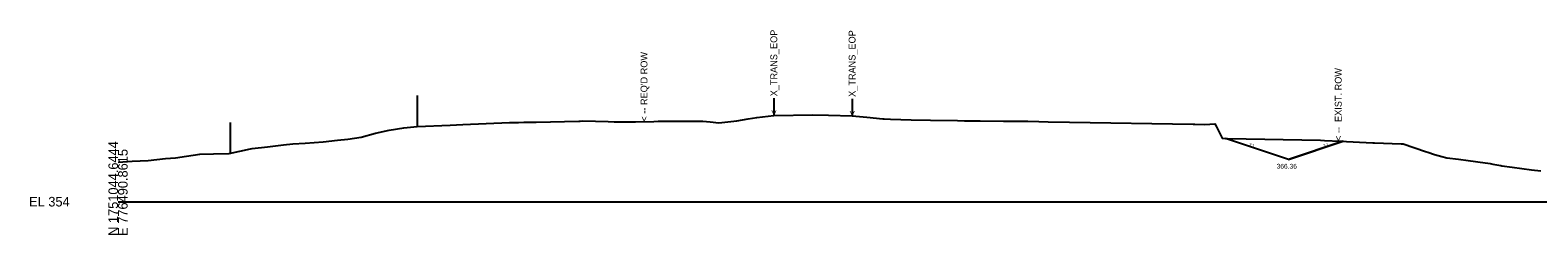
# Model space of a CAD drawing. Extents: x 776426 to 854588, y 1736205 to 1756790.
# Drawn here: x 805845.1 to 806285.9, y 1736205.1 to 1736264.9 of the extents above; entities that cross this region are included whole.
import ezdxf

# ---------------------------------------------------------------- set-up
doc = ezdxf.new("R2010")
doc.units = 0
for name, color, linetype in [('DTM CONTOURS_MAJOR_TX', 7, 'Continuous'), ('DTM_X_FLOW_ARROWS', 7, 'Continuous'), ('TRANS_UNPAVED_SHOULDERS', 7, 'Continuous'), ('X_TRANS_EOP', 7, 'Continuous'), ('XS_M_SHAPES_EARTHWORK', 7, 'Continuous'), ('XS_P_FINISHED_GRADE', 7, 'Continuous'), ('XS_P_ROW', 7, 'Continuous'), ('XS_P_TX_DCH', 7, 'Continuous'), ('XS_P_TX_FS_BS', 7, 'Continuous'), ('XS_X_PAVEMENT', 7, 'Continuous'), ('XS_X_ROW', 7, 'Continuous')]:
    doc.layers.add(name, color=color, linetype=linetype)

msp = doc.modelspace()

# ---------------------------------------------------------------- linework, layer by layer
at = {"layer": 'DTM CONTOURS_MAJOR_TX'}
msp.add_line((805870.79, 1736214.76), (806370.79, 1736214.76), dxfattribs=at)
at = {"layer": 'DTM_X_FLOW_ARROWS'}
msp.add_lwpolyline([(805870.79, 1736226.27), (805874.9, 1736226.59), (805879.55, 1736226.84), (805884.69, 1736227.34), (805887.54, 1736227.57), (805890.82, 1736228.02), (805892.77, 1736228.32), (805894.7, 1736228.63), (805898.66, 1736228.72), (805903.31, 1736228.83), (805909.55, 1736230.22), (805910.04, 1736230.33), (805914.5, 1736230.82), (805919.12, 1736231.33), (805921.85, 1736231.63), (805925.46, 1736231.88), (805930.79, 1736232.26), (805934.92, 1736232.77), (805937.97, 1736233.08), (805941.82, 1736233.66), (805946.1, 1736234.8), (805950.06, 1736235.63), (805954.35, 1736236.34), (805958.21, 1736236.78), (805967.88, 1736237.08), (805971.59, 1736237.36), (805985.19, 1736237.93), (805987.11, 1736237.92), (805987.82, 1736237.92), (805989.46, 1736238), (805993, 1736238.05), (806005.47, 1736238.33), (806005.92, 1736238.34), (806006.68, 1736238.36), (806014.04, 1736238.18), (806015.86, 1736238.14), (806022.03, 1736238.14), (806027.38, 1736238.24), (806028.65, 1736238.27), (806030.28, 1736238.26), (806041.74, 1736238.33), (806043.86, 1736238.1), (806046.42, 1736237.79), (806051.68, 1736238.42), (806055.02, 1736238.97), (806057.55, 1736239.39), (806062.5, 1736240), (806073.95, 1736240.11), (806078.53, 1736240.01), (806085.39, 1736239.83), (806089.69, 1736239.48), (806094.36, 1736239.02), (806094.79, 1736238.98), (806096.6, 1736238.9), (806102.7, 1736238.69), (806108.33, 1736238.55), (806116.23, 1736238.45), (806118.26, 1736238.42), (806120.96, 1736238.38), (806122.87, 1736238.37), (806129.65, 1736238.32), (806136.79, 1736238.31), (806139.95, 1736238.2), (806142.72, 1736238.13), (806148.92, 1736238.01), (806185.08, 1736237.4), (806185.58, 1736237.42), (806188.53, 1736237.37), (806191.43, 1736237.48), (806191.78, 1736236.79), (806193.59, 1736233.28), (806195.14, 1736233.25), (806222.27, 1736232.71), (806223.46, 1736232.64), (806228.06, 1736232.48), (806233.69, 1736232.15), (806237.61, 1736231.99), (806238.11, 1736231.94), (806245.92, 1736231.66), (806246.47, 1736231.64), (806252.97, 1736229.42), (806253.69, 1736229.2), (806255.65, 1736228.6), (806257.77, 1736227.92), (806259.26, 1736227.56), (806262.68, 1736227.19), (806263.3, 1736227.09), (806264.79, 1736226.92), (806268.28, 1736226.45), (806271.92, 1736225.88), (806272.69, 1736225.74), (806275.03, 1736225.33), (806275.35, 1736225.28), (806278.36, 1736224.82), (806283.97, 1736224.08), (806286.77, 1736223.8)], dxfattribs=at)
at = {"layer": 'TRANS_UNPAVED_SHOULDERS'}
for p, q in [((805958.23, 1736245.78), (805958.23, 1736236.78)), ((805958.23, 1736245.78), (805958.23, 1736236.78)), ((805903.6, 1736237.9), (805903.6, 1736228.9)), ((805903.6, 1736237.9), (805903.6, 1736228.9))]:
    msp.add_line(p, q, dxfattribs=at)
at = {"layer": 'X_TRANS_EOP'}
for p, q in [((806062.5, 1736245), (806062.5, 1736240)), ((806062.5, 1736245), (806062.5, 1736240)), ((806085.38, 1736244.83), (806085.38, 1736239.83)), ((806085.38, 1736244.83), (806085.38, 1736239.83))]:
    msp.add_line(p, q, dxfattribs=at)
at = {"layer": 'XS_M_SHAPES_EARTHWORK'}
msp.add_lwpolyline([(806195.14, 1736233.25), (806222.27, 1736232.71), (806223.46, 1736232.64), (806228.06, 1736232.48), (806228.9, 1736232.43), (806212.97, 1736227.12), (806194.56, 1736233.26)], close=True, dxfattribs=at)
at = {"layer": 'XS_P_FINISHED_GRADE'}
for q in [(806194.56, 1736233.26), (806228.9, 1736232.43)]:
    msp.add_line((806212.97, 1736227.12), q, dxfattribs=at)

# ---------------------------------------------------------------- texts
at = {"layer": 'DTM CONTOURS_MAJOR_TX'}
for s, p in [('N 1751044.6444', (805870.79, 1736204.76)), ('E 776490.8615', (805873.59, 1736204.76))]:
    msp.add_text(s, height=2.8, rotation=90, dxfattribs=at).set_placement(p)
msp.add_text('EL 354', height=2.8, dxfattribs=at).set_placement((805844.79, 1736213.36))
at = {"layer": 'XS_P_ROW'}
msp.add_text("< -- REQ'D ROW", height=2, rotation=90, dxfattribs=at).set_placement((806025.55, 1736238.18))
at = {"layer": 'XS_P_TX_DCH'}
msp.add_text('366.36', height=1.4, dxfattribs=at).set_placement((806209.5, 1736224.42))
at = {"layer": 'XS_P_TX_FS_BS'}
for rotation, p in [(341.5651, (806201.39, 1736231.18)), (18.4349, (806223.27, 1736230.75))]:
    msp.add_text('3:1', height=0.8, rotation=rotation, dxfattribs=at).set_placement(p)
at = {"layer": 'XS_X_PAVEMENT'}
for p in [(806063.5, 1736240), (806086.38, 1736239.83)]:
    msp.add_text('< --  X_TRANS_EOP', height=2, rotation=90, dxfattribs=at).set_placement(p)
at = {"layer": 'XS_X_ROW'}
msp.add_text('< --  EXIST. ROW', height=2, rotation=90, dxfattribs=at).set_placement((806228.5, 1736232.5))

doc.saveas('drawing.dxf')
